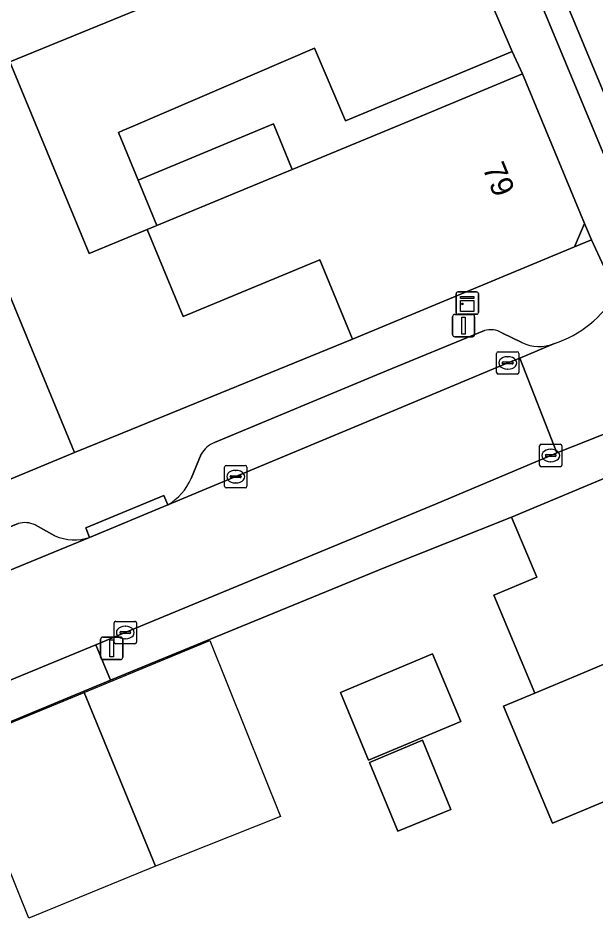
# Model space of a CAD drawing. Extents: x 159371 to 159986, y 382987 to 383597.
# Drawn here: x 159910.85 to 159936.68, y 383362.53 to 383403.47 of the extents above; entities that cross this region are included whole.
import ezdxf

# ---------------------------------------------------------------- set-up
doc = ezdxf.new("R2010")
doc.units = 0
for name, color, linetype in [('IMGEO_Erf', 7, 'Continuous'), ('IMGEO_Kast', 7, 'Continuous'), ('IMGEO_Kolk', 7, 'Continuous'), ('IMGEO_Lichtmast', 7, 'Continuous'), ('IMGEO_Muur', 7, 'Continuous'), ('IMGEO_Pand', 7, 'Continuous'), ('IMGEO_Pand_nummerreeks', 7, 'Continuous'), ('IMGEO_Pand_vergunning_verleend', 7, 'Continuous'), ('IMGEO_Parkeervlak_open', 7, 'Continuous'), ('IMGEO_Rijbaan_lokaal_gesloten', 7, 'Continuous'), ('IMGEO_Rijbaan_lokaal_open', 7, 'Continuous'), ('IMGEO_Voetpad_open', 7, 'Continuous')]:
    doc.layers.add(name, color=color, linetype=linetype)

msp = doc.modelspace()

# ---------------------------------------------------------------- linework, layer by layer
at = {"layer": 'IMGEO_Erf'}
for points in [[(159915.325, 383398.371), (159916.207, 383396.235), (159922.266, 383398.746), (159923.108, 383396.716), (159928.791, 383399.071), (159933.41, 383400.985), (159932.941, 383401.982), (159928.324, 383400.063), (159925.483, 383398.882), (159924.094, 383402.131), (159915.982, 383398.653), (159915.519, 383398.455)], [(159925.266, 383373.321), (159929.372, 383375.045), (159930.64, 383372.023), (159926.515, 383370.292)], [(159927.826, 383367.112), (159926.557, 383370.189), (159928.931, 383371.185), (159930.2, 383368.085)]]:
    msp.add_lwpolyline(points, close=True, dxfattribs=at)
for points in [[(159909.884, 383392.444), (159911.446, 383388.674), (159913.361, 383384.054), (159915.491, 383384.923), (159925.799, 383389.128), (159924.333, 383392.668), (159918.226, 383390.137), (159916.615, 383394.023), (159914.018, 383392.946), (159910.463, 383401.527)], [(159938.072, 383368.867), (159934.754, 383367.475), (159932.558, 383372.707), (159933.96, 383373.295), (159932.124, 383377.671), (159934.042, 383378.476), (159932.918, 383381.155), (159927.224, 383378.895), (159915.917, 383374.262), (159914.973, 383373.871), (159906.767, 383370.475), (159908.377, 383366.545), (159911.987, 383357.288)]]:
    msp.add_lwpolyline(points, dxfattribs=at)
at = {"layer": 'IMGEO_Kast'}
for p, q in [((159930.433, 383390.308), (159930.433, 383391.149)), ((159930.433, 383391.149), (159930.433, 383390.308)), ((159930.508, 383391.233), (159931.349, 383391.233)), ((159931.349, 383391.233), (159930.508, 383391.233)), ((159931.433, 383391.158), (159931.433, 383390.317)), ((159931.433, 383390.317), (159931.433, 383391.158)), ((159931.358, 383390.233), (159930.517, 383390.233)), ((159930.517, 383390.233), (159931.358, 383390.233))]:
    msp.add_line(p, q, dxfattribs=at)
for points in [[(159930.628, 383391.023), (159931.228, 383391.023), (159931.228, 383390.938), (159930.628, 383390.938), (159930.628, 383391.023)], [(159930.628, 383390.848), (159931.228, 383390.848), (159931.228, 383390.359), (159930.628, 383390.359), (159930.628, 383390.848)]]:
    msp.add_lwpolyline(points, dxfattribs=at)
msp.add_circle((159930.712, 383390.697), 0.0377, dxfattribs=at)
for centre, start, end in [((159930.511, 383391.155), 92.4484, 184.2845), ((159930.511, 383391.155), 92.4484, 184.2845), ((159931.355, 383391.155), 2.4484, 94.2845), ((159931.355, 383391.155), 2.4484, 94.2845), ((159930.511, 383390.311), 182.4484, 274.2845), ((159930.511, 383390.311), 182.4484, 274.2845), ((159931.355, 383390.311), 272.4484, 4.2845), ((159931.355, 383390.311), 272.4484, 4.2845)]:
    msp.add_arc(centre, 0.0779, start, end, dxfattribs=at)
at = {"layer": 'IMGEO_Kolk'}
for p, q in [((159932.244, 383387.632), (159932.244, 383388.484)), ((159932.319, 383388.558), (159933.171, 383388.558)), ((159932.732, 383388.338), (159932.757, 383388.338)), ((159933.245, 383388.484), (159933.245, 383387.632)), ((159932.503, 383388.052), (159932.503, 383388.064)), ((159932.941, 383388.015), (159932.543, 383388.015)), ((159932.546, 383388.101), (159932.944, 383388.101)), ((159932.987, 383388.064), (159932.987, 383388.052)), ((159933.171, 383387.558), (159932.319, 383387.558)), ((159932.755, 383387.778), (159932.73, 383387.778)), ((159934.168, 383383.492), (159934.168, 383384.344)), ((159934.243, 383384.418), (159935.095, 383384.418)), ((159934.656, 383384.198), (159934.681, 383384.198)), ((159935.169, 383384.344), (159935.169, 383383.492)), ((159934.427, 383383.912), (159934.427, 383383.924)), ((159934.865, 383383.875), (159934.467, 383383.875)), ((159934.47, 383383.961), (159934.868, 383383.961)), ((159934.911, 383383.924), (159934.911, 383383.912)), ((159920.074, 383382.545), (159920.074, 383383.397)), ((159920.149, 383383.471), (159921.001, 383383.471)), ((159921.075, 383383.397), (159921.075, 383382.545)), ((159935.095, 383383.418), (159934.243, 383383.418)), ((159934.679, 383383.638), (159934.654, 383383.638)), ((159920.333, 383382.965), (159920.333, 383382.977)), ((159920.771, 383382.928), (159920.373, 383382.928)), ((159920.376, 383383.014), (159920.774, 383383.014)), ((159920.562, 383383.251), (159920.587, 383383.251)), ((159920.817, 383382.977), (159920.817, 383382.965)), ((159920.585, 383382.691), (159920.56, 383382.691)), ((159921.001, 383382.471), (159920.149, 383382.471)), ((159915.135, 383375.575), (159915.135, 383376.427)), ((159915.21, 383376.501), (159916.062, 383376.501)), ((159916.136, 383376.427), (159916.136, 383375.575)), ((159915.394, 383375.995), (159915.394, 383376.007)), ((159915.437, 383376.044), (159915.835, 383376.044)), ((159915.623, 383376.281), (159915.648, 383376.281)), ((159915.878, 383376.007), (159915.878, 383375.995)), ((159915.832, 383375.958), (159915.434, 383375.958)), ((159915.646, 383375.721), (159915.621, 383375.721)), ((159916.062, 383375.501), (159915.21, 383375.501))]:
    msp.add_line(p, q, dxfattribs=at)
for points in [[(159932.244, 383387.632), (159932.244, 383388.484)], [(159932.319, 383388.558), (159933.171, 383388.558)], [(159933.245, 383388.484), (159933.245, 383387.632)], [(159933.171, 383387.558), (159932.319, 383387.558)], [(159934.168, 383383.492), (159934.168, 383384.344)], [(159934.243, 383384.418), (159935.095, 383384.418)], [(159935.169, 383384.344), (159935.169, 383383.492)], [(159920.074, 383382.545), (159920.074, 383383.397)], [(159920.149, 383383.471), (159921.001, 383383.471)], [(159921.075, 383383.397), (159921.075, 383382.545)], [(159935.095, 383383.418), (159934.243, 383383.418)], [(159921.001, 383382.471), (159920.149, 383382.471)], [(159915.135, 383375.575), (159915.135, 383376.427)], [(159915.21, 383376.501), (159916.062, 383376.501)], [(159916.136, 383376.427), (159916.136, 383375.575)], [(159916.062, 383375.501), (159915.21, 383375.501)]]:
    msp.add_lwpolyline(points, dxfattribs=at)
for centre, radius, start, end in [((159932.321, 383388.482), 0.0765, 91.552, 178.448), ((159932.321, 383388.482), 0.0765, 91.552, 178.448), ((159933.169, 383388.482), 0.0765, 1.552, 88.448), ((159933.169, 383388.482), 0.0765, 1.552, 88.448), ((159932.543, 383388.061), 0.0403, 85.8775, 175.7526), ((159932.54, 383388.051), 0.0366, 178.938, 274.7102), ((159932.944, 383388.058), 0.043, 264.8664, 352.4533), ((159932.948, 383388.063), 0.0386, 1.7309, 96.639), ((159932.321, 383387.634), 0.0765, 181.552, 268.448), ((159932.321, 383387.634), 0.0765, 181.552, 268.448), ((159933.169, 383387.634), 0.0765, 271.552, 358.448), ((159933.169, 383387.634), 0.0765, 271.552, 358.448), ((159934.245, 383384.342), 0.0765, 91.552, 178.448), ((159934.245, 383384.342), 0.0765, 91.552, 178.448), ((159935.093, 383384.342), 0.0765, 1.552, 88.448), ((159935.093, 383384.342), 0.0765, 1.552, 88.448), ((159934.467, 383383.921), 0.0403, 85.8775, 175.7526), ((159934.464, 383383.911), 0.0366, 178.938, 274.7102), ((159934.868, 383383.918), 0.043, 264.8664, 352.4533), ((159934.872, 383383.923), 0.0386, 1.7309, 96.639), ((159920.151, 383383.395), 0.0765, 91.552, 178.448), ((159920.151, 383383.395), 0.0765, 91.552, 178.448), ((159920.999, 383383.395), 0.0765, 1.552, 88.448), ((159920.999, 383383.395), 0.0765, 1.552, 88.448), ((159934.245, 383383.494), 0.0765, 181.552, 268.448), ((159934.245, 383383.494), 0.0765, 181.552, 268.448), ((159935.093, 383383.494), 0.0765, 271.552, 358.448), ((159935.093, 383383.494), 0.0765, 271.552, 358.448), ((159920.373, 383382.974), 0.0403, 85.8775, 175.7526), ((159920.37, 383382.964), 0.0366, 178.938, 274.7102), ((159920.774, 383382.971), 0.043, 264.8664, 352.4533), ((159920.778, 383382.976), 0.0386, 1.7309, 96.639), ((159920.151, 383382.547), 0.0765, 181.552, 268.448), ((159920.151, 383382.547), 0.0765, 181.552, 268.448), ((159920.999, 383382.547), 0.0765, 271.552, 358.448), ((159920.999, 383382.547), 0.0765, 271.552, 358.448), ((159915.212, 383376.425), 0.0765, 91.552, 178.448), ((159915.212, 383376.425), 0.0765, 91.552, 178.448), ((159916.06, 383376.425), 0.0765, 1.552, 88.448), ((159916.06, 383376.425), 0.0765, 1.552, 88.448), ((159915.434, 383376.004), 0.0403, 85.8775, 175.7526), ((159915.431, 383375.994), 0.0366, 178.938, 274.7102), ((159915.835, 383376.001), 0.043, 264.8664, 352.4533), ((159915.839, 383376.006), 0.0386, 1.7309, 96.639), ((159915.212, 383375.577), 0.0765, 181.552, 268.448), ((159915.212, 383375.577), 0.0765, 181.552, 268.448), ((159916.06, 383375.577), 0.0765, 271.552, 358.448), ((159916.06, 383375.577), 0.0765, 271.552, 358.448)]:
    msp.add_arc(centre, radius, start, end, dxfattribs=at)
for centre, major_axis, ratio, start_param, end_param in [((159932.731, 383388.058), (-0.387, 0.002), 0.722429, 4.712389, 7.853982), ((159932.756, 383388.058), (-0.39, 0.002), 0.717154, 1.570796, 4.712389), ((159934.655, 383383.918), (-0.387, 0.002), 0.722429, 4.712389, 7.853982), ((159934.68, 383383.918), (-0.39, 0.002), 0.717154, 1.570796, 4.712389), ((159920.561, 383382.971), (-0.387, 0.002), 0.722429, 4.712389, 7.853982), ((159920.586, 383382.971), (-0.39, 0.002), 0.717154, 1.570796, 4.712389), ((159915.622, 383376.001), (-0.387, 0.002), 0.722429, 4.712389, 7.853982), ((159915.647, 383376.001), (-0.39, 0.002), 0.717154, 1.570796, 4.712389)]:
    msp.add_ellipse(centre, major_axis=major_axis, ratio=ratio, start_param=start_param, end_param=end_param, dxfattribs=at)
at = {"layer": 'IMGEO_Lichtmast'}
for p, q in [((159930.275, 383389.327), (159930.275, 383390.127)), ((159930.275, 383390.127), (159930.275, 383389.327)), ((159930.375, 383390.227), (159931.165, 383390.227)), ((159931.165, 383390.227), (159930.375, 383390.227)), ((159931.265, 383390.127), (159931.265, 383389.327)), ((159931.265, 383389.327), (159931.265, 383390.127)), ((159931.165, 383389.227), (159930.375, 383389.227)), ((159930.375, 383389.227), (159931.165, 383389.227)), ((159914.53, 383374.894), (159914.53, 383375.694)), ((159914.53, 383375.694), (159914.53, 383374.894)), ((159914.63, 383375.794), (159915.42, 383375.794)), ((159915.42, 383375.794), (159914.63, 383375.794)), ((159915.52, 383375.694), (159915.52, 383374.894)), ((159915.52, 383374.894), (159915.52, 383375.694)), ((159915.42, 383374.794), (159914.63, 383374.794)), ((159914.63, 383374.794), (159915.42, 383374.794))]:
    msp.add_line(p, q, dxfattribs=at)
for points in [[(159930.695, 383390.102), (159930.845, 383390.102), (159930.845, 383389.352), (159930.695, 383389.352), (159930.695, 383390.102)], [(159914.95, 383375.669), (159915.1, 383375.669), (159915.1, 383374.919), (159914.95, 383374.919), (159914.95, 383375.669)]]:
    msp.add_lwpolyline(points, dxfattribs=at)
for centre, start, end in [((159930.375, 383390.127), 90, 180), ((159930.375, 383390.127), 90, 180), ((159931.165, 383390.127), 0, 90), ((159931.165, 383390.127), 360, 90), ((159930.375, 383389.327), 180, 270), ((159930.375, 383389.327), 180, 270), ((159931.165, 383389.327), 270, 0), ((159931.165, 383389.327), 270, 0), ((159914.63, 383375.694), 90, 180), ((159914.63, 383375.694), 90, 180), ((159915.42, 383375.694), 0, 90), ((159915.42, 383375.694), 360, 90), ((159914.63, 383374.894), 180, 270), ((159914.63, 383374.894), 180, 270), ((159915.42, 383374.894), 270, 0), ((159915.42, 383374.894), 270, 0)]:
    msp.add_arc(centre, 0.1, start, end, dxfattribs=at)
at = {"layer": 'IMGEO_Muur'}
msp.add_lwpolyline([(159925.799, 383389.128), (159915.491, 383384.923)], dxfattribs=at)
at = {"layer": 'IMGEO_Pand'}
for points in [[(159929.666, 383409.619), (159926.604, 383416.76), (159923.474, 383415.417), (159923.137, 383416.203), (159914.242, 383412.388), (159898.736, 383406.04), (159902.048, 383398.093), (159910.463, 383401.527), (159916.891, 383404.15)], [(159929.666, 383409.619), (159916.891, 383404.15), (159910.463, 383401.527), (159914.018, 383392.946), (159916.615, 383394.023), (159917.049, 383394.203), (159916.207, 383396.235), (159915.325, 383398.371), (159915.519, 383398.455), (159915.982, 383398.653), (159924.094, 383402.131), (159925.483, 383398.882), (159928.324, 383400.063), (159932.941, 383401.982)], [(159933.41, 383400.985), (159928.791, 383399.071), (159923.108, 383396.716), (159917.049, 383394.203), (159916.615, 383394.023), (159918.226, 383390.137), (159924.333, 383392.668), (159925.799, 383389.128), (159935.731, 383393.244), (159936.186, 383394.288)], [(159917.049, 383394.203), (159923.108, 383396.716), (159922.266, 383398.746), (159916.207, 383396.235)], [(159903.049, 383395.65), (159908.654, 383382.104), (159913.361, 383384.054), (159911.446, 383388.674), (159909.884, 383392.444), (159907.734, 383397.602)], [(159940.324, 383384.262), (159932.918, 383381.155), (159934.042, 383378.476), (159932.124, 383377.671), (159933.96, 383373.295), (159935.878, 383374.1), (159943.284, 383377.207)], [(159943.284, 383377.207), (159935.878, 383374.1), (159933.96, 383373.295), (159932.558, 383372.707), (159934.754, 383367.475), (159938.072, 383368.867), (159938.882, 383366.939), (159946.289, 383370.045)], [(159925.266, 383373.321), (159926.515, 383370.292), (159930.64, 383372.023), (159929.372, 383375.045)], [(159927.826, 383367.112), (159930.2, 383368.085), (159928.931, 383371.185), (159926.557, 383370.189)]]:
    msp.add_lwpolyline(points, close=True, dxfattribs=at)
at = {"layer": 'IMGEO_Pand_vergunning_verleend'}
for points in [[(159913.794, 383373.318), (159919.411, 383375.643), (159922.58, 383367.775), (159916.985, 383365.545)], [(159908.175, 383371.012), (159913.794, 383373.318), (159916.985, 383365.545), (159911.323, 383363.221)]]:
    msp.add_lwpolyline(points, close=True, dxfattribs=at)
at = {"layer": 'IMGEO_Parkeervlak_open'}
for points in [[(159931.699, 383389.509), (159927.075, 383387.595), (159919.621, 383384.502)], [(159933.377, 383388.972), (159932.484, 383389.404)], [(159917.544, 383381.715), (159927.798, 383385.983), (159932.746, 383388.057), (159933.283, 383388.264), (159934.831, 383388.922)], [(159919.028, 383383.983), (159918.58, 383382.883)], [(159910.848, 383380.871), (159876.516, 383366.772)], [(159912.486, 383380.324), (159911.597, 383380.814)], [(159874.665, 383364.08), (159894.206, 383372.109), (159896.76, 383373.158), (159914.033, 383380.255)]]:
    msp.add_lwpolyline(points, dxfattribs=at)
for centre, radius, start, end in [((159931.964, 383388.502), 1.042, 60.0375, 104.7254), ((159934.16, 383390.575), 1.784, 243.9611, 292.0999), ((159920.185, 383383.259), 1.365, 114.4196, 147.9659), ((159916.27, 383383.889), 2.519, 300.3776, 336.4773), ((159911.149, 383379.883), 1.033, 64.3226, 106.9735), ((159913.352, 383382.364), 2.216, 246.9977, 287.8946)]:
    msp.add_arc(centre, radius, start, end, dxfattribs=at)
at = {"layer": 'IMGEO_Rijbaan_lokaal_gesloten'}
msp.add_lwpolyline([(159930.657, 383412.742), (159937.376, 383396.59), (159938.372, 383396.952), (159930.55, 383415.737)], dxfattribs=at)
at = {"layer": 'IMGEO_Rijbaan_lokaal_open'}
for points in [[(159896.507, 383502.966), (159894.117, 383501.311), (159895.58, 383498.934), (159896.28, 383497.634), (159897.404, 383495.183), (159900.129, 383488.781), (159911.403, 383461.749), (159918.901, 383443.595), (159930.55, 383415.737), (159938.372, 383396.952), (159940.105, 383397.581), (159940.105, 383397.581), (159908.349, 383474.342)], [(159896.76, 383373.158), (159898.484, 383368.948), (159906.023, 383372.039), (159914.314, 383375.45), (159915.632, 383376.002), (159929.511, 383381.743), (159934.668, 383383.919), (159934.949, 383384.031), (159933.283, 383388.264), (159932.746, 383388.057), (159927.798, 383385.983), (159917.544, 383381.715), (159914.033, 383380.255)]]:
    msp.add_lwpolyline(points, close=True, dxfattribs=at)
msp.add_lwpolyline([(159934.831, 383388.922), (159933.283, 383388.264), (159934.949, 383384.031), (159937.661, 383385.11)], dxfattribs=at)
msp.add_arc((159933.292, 383393.632), 4.955, 288.0973, 330.2371, dxfattribs=at)
at = {"layer": 'IMGEO_Voetpad_open'}
for points in [[(159938.129, 383394.694), (159937.477, 383396.347), (159937.376, 383396.59), (159930.657, 383412.742), (159928.132, 383418.79), (159927.173, 383418.387), (159925.426, 383422.549), (159926.385, 383422.952), (159925.951, 383423.98)], [(159929.666, 383409.619), (159932.941, 383401.982), (159933.41, 383400.985), (159936.186, 383394.288), (159936.488, 383393.558), (159937.593, 383391.172)], [(159937.593, 383391.172), (159936.488, 383393.558), (159935.731, 383393.244), (159925.799, 383389.128), (159915.491, 383384.923), (159913.361, 383384.054), (159908.654, 383382.104), (159903.907, 383380.136), (159900.325, 383378.652), (159897.701, 383377.573), (159894.099, 383376.108), (159893.678, 383375.937), (159893.256, 383375.765), (159889.68, 383374.283), (159887.111, 383373.195), (159883.622, 383371.749), (159880.134, 383370.303), (159877.483, 383369.202)], [(159919.621, 383384.502), (159927.075, 383387.595), (159931.699, 383389.509)], [(159932.484, 383389.404), (159933.377, 383388.972)], [(159937.661, 383385.11), (159934.949, 383384.031), (159934.668, 383383.919), (159929.511, 383381.743), (159915.632, 383376.002), (159914.314, 383375.45), (159914.973, 383373.871), (159915.917, 383374.262), (159927.224, 383378.895), (159932.918, 383381.155), (159940.324, 383384.262)], [(159918.58, 383382.883), (159919.028, 383383.983)], [(159914.033, 383380.255), (159913.876, 383380.678), (159917.353, 383382.125), (159917.544, 383381.715)], [(159876.516, 383366.772), (159910.848, 383380.871)], [(159911.597, 383380.814), (159912.486, 383380.324)]]:
    msp.add_lwpolyline(points, dxfattribs=at)
for points in [[(159936.186, 383394.288), (159935.731, 383393.244), (159936.488, 383393.558)], [(159914.033, 383380.255), (159917.544, 383381.715), (159917.353, 383382.125), (159913.876, 383380.678)], [(159914.314, 383375.45), (159906.023, 383372.039), (159906.767, 383370.475), (159914.973, 383373.871)]]:
    msp.add_lwpolyline(points, close=True, dxfattribs=at)
for centre, radius, start, end in [((159933.292, 383393.632), 4.955, 288.0973, 330.2371), ((159931.964, 383388.502), 1.042, 60.0375, 104.7254), ((159934.16, 383390.575), 1.784, 243.9611, 292.0999), ((159920.185, 383383.259), 1.365, 114.4196, 147.9659), ((159916.27, 383383.889), 2.519, 300.3776, 336.4773), ((159911.149, 383379.883), 1.033, 64.3226, 106.9735), ((159913.352, 383382.364), 2.216, 246.9977, 287.8946)]:
    msp.add_arc(centre, radius, start, end, dxfattribs=at)

# ---------------------------------------------------------------- texts
at = {"layer": 'IMGEO_Pand_nummerreeks'}
msp.add_text('79', height=1, rotation=292.5113, dxfattribs=at).set_placement((159931.602, 383396.779))

doc.saveas('drawing.dxf')
